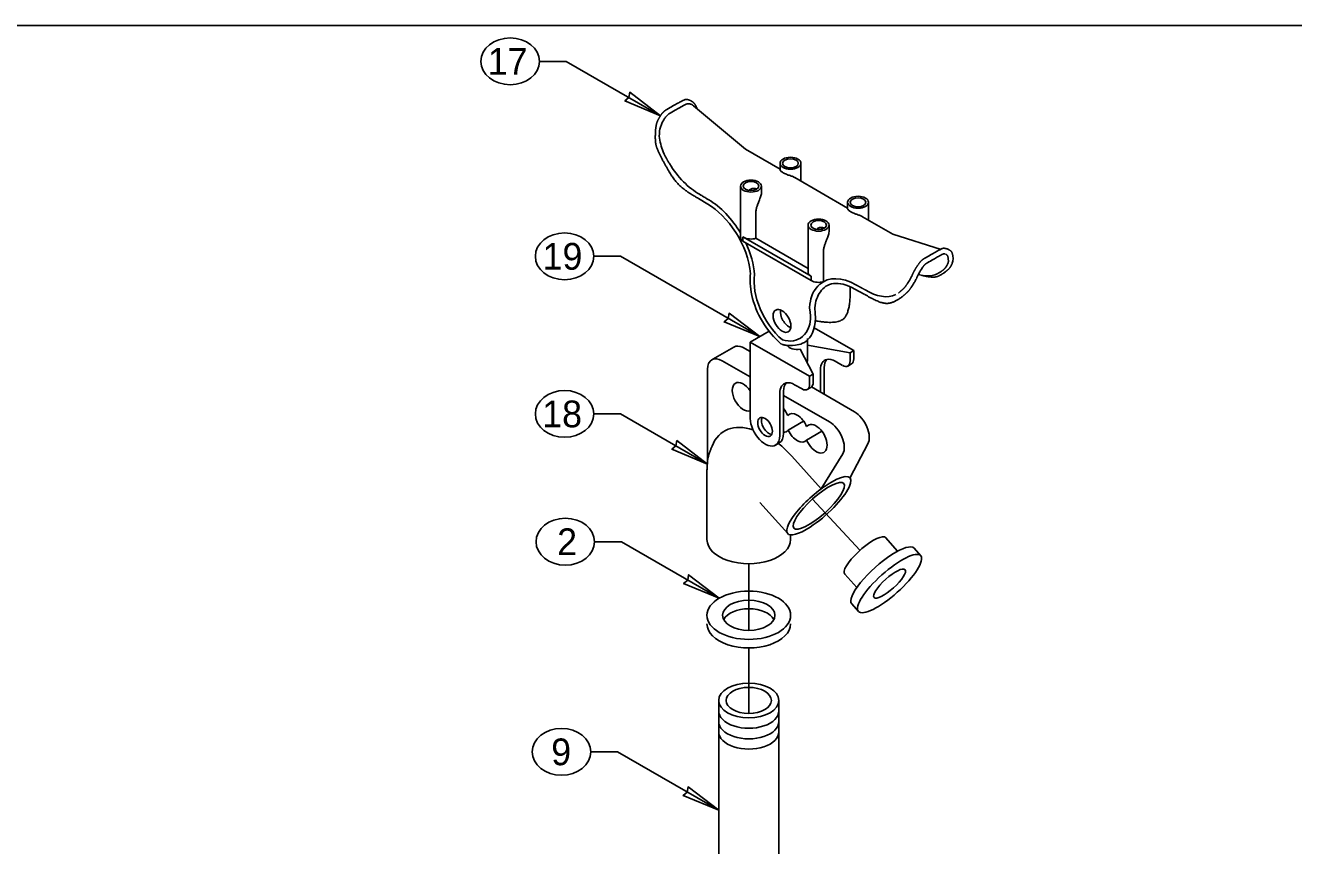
# Model space of a CAD drawing. Extents: x 99862 to 104211, y 98939 to 105076.
# Drawn here: x 100620 to 101379, y 104585 to 105076 of the extents above; entities that cross this region are included whole.
import ezdxf

# ---------------------------------------------------------------- set-up
doc = ezdxf.new("R2010")
doc.units = 0
for name, color, linetype in [('Level 1', 7, 'Continuous'), ('Level 11', 7, 'Continuous'), ('Level 15', 7, 'Continuous'), ('Level 17', 7, 'Continuous'), ('Level 18', 7, 'Continuous'), ('Level 19', 7, 'Continuous'), ('Level 2', 7, 'Continuous'), ('Level 20', 7, 'Continuous'), ('Level 4', 7, 'Continuous'), ('Level 5', 7, 'Continuous'), ('Level 6', 7, 'Continuous'), ('Level 9', 7, 'Continuous')]:
    doc.layers.add(name, color=color, linetype=linetype)

msp = doc.modelspace()

# ---------------------------------------------------------------- linework, layer by layer
at = {"layer": 'Level 1'}
msp.add_lwpolyline([(99862, 102999.5), (103151, 102999.5), (103151, 105075.5), (99862, 105075.5)], close=True, dxfattribs=at)
at = {"layer": 'Level 11'}
msp.add_ellipse((101053.04, 104722.69), major_axis=(15.62, 0), ratio=0.57735, dxfattribs=at)
for major_axis, start_param, end_param in [((-15.62, 0), 3.428349, 5.996429), ((-25, 0), 6.283185, 9.424778)]:
    msp.add_ellipse((101053.04, 104717.59), major_axis=major_axis, ratio=0.57735, start_param=start_param, end_param=end_param, dxfattribs=at)
at = {"layer": 'Level 15'}
for p, q in [((100927.89, 105053.96), (100943.89, 105053.96)), ((101000.18, 105021.46), (100943.89, 105053.96)), ((100960.4, 104937.38), (100976.4, 104937.38)), ((101059.56, 104889.37), (100976.4, 104937.38)), ((100960.4, 104843.13), (100976.4, 104843.13)), ((101028.35, 104813.14), (100976.4, 104843.13)), ((101119.52, 104761.57), (101091.2, 104792.24)), ((100960.83, 104766.69), (100976.83, 104766.69)), ((101035.37, 104732.9), (100976.83, 104766.69)), ((101053.04, 104713.67), (101053.04, 104753.52)), ((101053.04, 104664), (101053.04, 104703.15)), ((100958.51, 104641.04), (100974.51, 104641.04)), ((101035.04, 104606.09), (100974.51, 104641.04))]:
    msp.add_line(p, q, dxfattribs=at)
for points in [[(101000.18, 105021.46), (100978.92, 105030.29), (100981.33, 105032.35), (100981.9, 105035.46)], [(101059.56, 104889.37), (101038.29, 104898.2), (101040.7, 104900.26), (101041.28, 104903.37)], [(101028.35, 104813.14), (101007.08, 104821.97), (101009.49, 104824.03), (101010.07, 104827.14)], [(101035.37, 104732.9), (101014.1, 104741.72), (101016.51, 104743.78), (101017.09, 104746.9)], [(101035.04, 104606.09), (101013.78, 104614.92), (101016.19, 104616.97), (101016.77, 104620.09)]]:
    msp.add_lwpolyline(points, close=True, dxfattribs=at)
at = {"layer": 'Level 17'}
for p, q in [((101051.02, 105001.52), (101020.01, 105027.39)), ((101071.72, 104989.57), (101051.02, 105001.52)), ((101071.72, 104993.02), (101071.72, 104989.16)), ((101084.22, 104982.36), (101084.22, 104993.02)), ((101112.14, 104966.23), (101080.65, 104984.42)), ((101048.1, 104979.39), (101048.1, 104948.77)), ((101060.6, 104975.53), (101060.6, 104979.39)), ((101022.99, 104972.01), (101028.49, 104968.61)), ((101112.14, 104969.69), (101112.14, 104965.83)), ((101124.64, 104959.02), (101124.64, 104969.69)), ((101057.3, 104962.72), (101057.3, 104948.14)), ((101139.16, 104950.64), (101121.07, 104961.08)), ((101088.52, 104956.05), (101088.52, 104927.98)), ((101101.02, 104952.19), (101101.02, 104956.05)), ((101049.55, 104948.99), (101049.57, 104949)), ((101049.55, 104948.99), (101049.55, 104946.44)), ((101049.93, 104948.77), (101049.55, 104948.99)), ((101090.35, 104922.88), (101049.55, 104946.44)), ((101049.57, 104949), (101049.57, 104946.44)), ((101090.35, 104925.43), (101049.93, 104948.77)), ((101057.3, 104948.14), (101088.52, 104930.11)), ((101168.03, 104941.38), (101139.16, 104950.64)), ((101097.72, 104939.39), (101097.72, 104922.25)), ((101090.35, 104925.43), (101090.35, 104922.88)), ((101116.55, 104917.76), (101122.06, 104914.81))]:
    msp.add_line(p, q, dxfattribs=at)
for centre, major_axis, ratio, start_param, end_param in [((101022.89, 105004.42), (-17.72, 31.29), 0.57735, 1.6138, 2.395219), ((101029.05, 104939.26), (-19.52, 33.81), 0.57735, 4.736377, 5.49473), ((101054.35, 104948.77), (-6.25, 0), 0.57735, 6.283185, 6.98269), ((101054.35, 104951.32), (-6.25, 0), 0.57735, 0.699505, 0.785398), ((101054.35, 104951.32), (-6.25, 0), 0.57735, 0.785398, 2.061945), ((101029.05, 104939.26), (-19.52, 33.81), 0.57735, 4.022982, 4.565814), ((101078.65, 104909.31), (-15.86, 27.48), 0.57735, 0.616549, 2.107388), ((101094.77, 104927.98), (-6.25, 0), 0.57735, 6.283185, 7.068583), ((101094.77, 104925.43), (6.25, 0), 0.57735, 3.926991, 5.203538), ((101117.2, 104888.37), (-19.52, 33.81), 0.57735, 5.500844, 6.398051), ((101147.91, 104959.93), (-18.75, 32.48), 0.577329, 2.604955, 3.160056), ((101123.69, 104946.07), (-17.98, 31.14), 0.57735, 2.31717, 3.098589), ((101077.22, 104901.24), (3.75, -6.5), 0.57735, 3.754385, 5.670393), ((101067.6, 104915.69), (15.86, -27.48), 0.57735, 5.746594, 6.3945), ((101067.6, 104915.69), (15.86, -27.48), 0.57735, 0.13318472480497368, 0.13318473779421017)]:
    msp.add_ellipse(centre, major_axis=major_axis, ratio=ratio, start_param=start_param, end_param=end_param, dxfattribs=at)
for centre, major_axis in [((101077.97, 104993.02), (-6.25, 0)), ((101077.97, 104993.02), (-4.69, 0)), ((101054.35, 104979.39), (-6.25, 0)), ((101054.35, 104979.39), (4.69, 0)), ((101118.39, 104969.69), (6.25, 0)), ((101118.39, 104969.69), (4.69, 0)), ((101094.77, 104956.05), (6.25, 0)), ((101094.77, 104956.05), (-4.69, 0)), ((101072.91, 104898.75), (3.75, -6.5))]:
    msp.add_ellipse(centre, major_axis=major_axis, ratio=0.57735, dxfattribs=at)
for points, degree in [([(101017.26, 105030.92), (101015.78, 105031.33), (101014.12, 105030.99), (101004.13, 105025.26)], 2), ([(101017.78, 105028.53), (101017.28, 105028.63), (101016.75, 105028.63), (101015.62, 105028.42), (101015.02, 105028.2), (101005.99, 105023.01)], 3), ([(101022.01, 105026.11), (101020.95, 105028.32), (101019.39, 105030), (101017.26, 105030.92)], 2), ([(101020.01, 105027.38), (101019.34, 105027.95), (101018.61, 105028.35), (101017.78, 105028.53)], 2), ([(101000.08, 105021.29), (100998.54, 105018.73), (100997.57, 105015.8), (100997.31, 105012.91)], 2), ([(101004.13, 105025.26), (101002.69, 105024.39), (101001.31, 105023.06), (101000.08, 105021.29)], 2), ([(101005.99, 105023.01), (101005.41, 105022.65), (101004.81, 105022.18), (101003.69, 105021.1), (101003.16, 105020.48), (101002.66, 105019.81)], 3), ([(100997.32, 105012.91), (100996.88, 105007.06), (100998.19, 105001.07), (101001.03, 104995.89)], 2), ([(101002.66, 105019.81), (101001.93, 105018.73), (101001.32, 105017.53), (101000.35, 105015.05), (101000, 105013.77), (100999.73, 105012.49)], 3), ([(100999.73, 105012.49), (100999.4, 105009.8), (100999.68, 105007.09), (101000.99, 105001.85), (101002.01, 104999.32), (101003.28, 104996.91)], 3), ([(101001.05, 104995.86), (101006.35, 104985.51), (101014.62, 104976.49), (101022.99, 104972.01)], 2), ([(101003.28, 104996.91), (101003.55, 104996.4), (101003.83, 104995.9), (101004.12, 104995.4)], 2), ([(101004.12, 104995.4), (101004.55, 104994.51), (101005.05, 104993.67), (101005.6, 104992.86)], 2), ([(101080.66, 104984.41), (101080.42, 104984.55), (101080.16, 104984.68), (101079.27, 104985.09), (101078.56, 104985.36), (101077.08, 104985.87), (101076.29, 104986.14), (101074.83, 104986.72), (101074.14, 104987.03), (101072.99, 104987.69), (101072.53, 104988.04), (101071.91, 104988.67), (101071.75, 104988.95), (101071.72, 104989.14), (101071.72, 104989.15), (101071.72, 104989.16)], 3), ([(101057.75, 104977.52), (101057.72, 104977.54), (101057.7, 104977.55), (101057.18, 104977.86), (101056.57, 104978), (101055.3, 104977.97), (101054.65, 104977.79), (101053.7, 104977.28), (101053.37, 104977.05), (101053.06, 104976.78)], 3), ([(101057.3, 104962.72), (101057.23, 104964.14), (101057.42, 104965.5), (101058.03, 104967.61), (101058.29, 104968.32), (101058.85, 104969.76), (101059.17, 104970.51), (101059.76, 104972), (101060.05, 104972.77), (101060.46, 104974.21), (101060.59, 104974.9), (101060.6, 104975.54)], 3), ([(101023.63, 104974.5), (101024.75, 104973.81), (101025.87, 104973.12), (101026.98, 104972.43), (101027.7, 104971.98), (101028.42, 104971.54), (101029.14, 104971.09)], 3), ([(101028.53, 104968.58), (101034.15, 104965.32), (101046.76, 104952.94), (101053.4, 104935.26), (101054.06, 104926.95)], 3), ([(101112.14, 104965.83), (101112.14, 104965.82), (101112.14, 104965.81), (101112.16, 104965.62), (101112.32, 104965.34), (101112.94, 104964.71), (101113.39, 104964.37), (101114.54, 104963.71), (101115.22, 104963.39), (101116.69, 104962.81), (101117.47, 104962.55), (101118.96, 104962.03), (101119.67, 104961.76), (101120.58, 104961.35), (101120.84, 104961.21), (101121.09, 104961.07)], 3), ([(101098.17, 104954.19), (101098.14, 104954.2), (101098.12, 104954.22), (101097.6, 104954.52), (101096.99, 104954.67), (101095.72, 104954.63), (101095.06, 104954.45), (101094.11, 104953.94), (101093.79, 104953.71), (101093.48, 104953.45)], 3), ([(101101.02, 104952.16), (101101, 104951.54), (101100.88, 104950.87), (101100.48, 104949.44), (101100.2, 104948.69), (101099.3, 104946.44), (101098.67, 104944.99), (101098.05, 104942.87), (101097.89, 104942.19), (101097.72, 104940.84), (101097.7, 104940.17), (101097.72, 104939.39)], 3), ([(101158.25, 104936.22), (101168.3, 104941.99), (101169.94, 104942.32), (101171.63, 104941.83)], 2), ([(101159.84, 104933.53), (101168.81, 104938.69), (101169.99, 104939.02), (101170.49, 104938.92)], 2), ([(101171.04, 104938.6), (101171.71, 104938.07), (101172.12, 104937.3), (101172.23, 104936.32)], 2), ([(101171.63, 104941.83), (101173.52, 104941.06), (101174.83, 104939.34), (101175.11, 104937.29)], 2), ([(101175.1, 104937.29), (101175.31, 104935.97), (101175.14, 104934.32), (101174.58, 104932.95), (101174.46, 104932.67)], 3), ([(101150.39, 104925.2), (101151.37, 104927.52), (101152.74, 104930.03), (101154.3, 104932.38)], 2), ([(101153.25, 104923.95), (101153.68, 104924.96), (101154.72, 104927.16), (101156.12, 104929.48), (101156.9, 104930.66)], 3), ([(101154.35, 104932.45), (101155.46, 104934.04), (101156.85, 104935.38), (101158.29, 104936.25)], 2), ([(101156.9, 104930.66), (101157.78, 104931.9), (101158.84, 104932.93), (101159.87, 104933.55)], 2), ([(101171.27, 104931.52), (101170.72, 104930.6), (101169.94, 104929.73), (101168.95, 104928.95)], 2), ([(101174.46, 104932.67), (101173.74, 104931.07), (101172.56, 104929.68), (101170.98, 104928.45)], 2), ([(101172.23, 104936.32), (101172.49, 104934.67), (101172.18, 104933.02), (101171.27, 104931.52)], 2), ([(101054.06, 104927.02), (101053.61, 104923.77), (101053.92, 104914.3), (101060.2, 104898.14), (101068.38, 104888.37), (101072.44, 104884.93)], 3), ([(101142.54, 104915.48), (101145.42, 104917.71), (101148.01, 104921), (101150.41, 104925.24)], 2), ([(101145.15, 104913.54), (101147.85, 104915.68), (101150.62, 104919.26), (101153.25, 104923.95)], 2), ([(101170.97, 104928.44), (101167.18, 104925.41), (101162.06, 104924.66), (101156.59, 104925.98)], 2), ([(101168.95, 104928.95), (101168.34, 104928.45), (101167.69, 104928.02), (101167, 104927.66)], 2), ([(101089.42, 104906.78), (101089.89, 104912.44), (101092.01, 104917.46), (101095.41, 104920.52), (101095.57, 104920.67)], 3), ([(101092.54, 104906.59), (101092.86, 104910.29), (101095.1, 104917.02), (101102.85, 104922.41), (101111.52, 104920.64), (101116.51, 104917.79)], 3), ([(101092.59, 104898.91), (101107.43, 104896.05), (101114.14, 104906.37), (101113.56, 104919.27)], 2), ([(101117.11, 104920.3), (101118.95, 104919.32), (101120.78, 104918.33), (101122.62, 104917.35)], 2), ([(101122.01, 104914.85), (101130.46, 104909.59), (101139.36, 104908.91), (101145.14, 104913.53)], 2), ([(101076.2, 104884.06), (101076.68, 104884.01), (101080.19, 104883.68), (101090.16, 104886.31), (101093.62, 104897.63), (101092.54, 104906.59)], 3), ([(101085.13, 104889.4), (101085.24, 104889.49), (101088.83, 104892.79), (101090.43, 104899.24), (101089.42, 104906.63)], 3), ([(101072.63, 104884.83), (101073.82, 104884.47), (101074.97, 104884.21), (101076.18, 104884.06)], 2)]:
    msp.add_open_spline(points, degree=degree, dxfattribs=at)
at = {"layer": 'Level 18'}
for p, q in [((101044.14, 104883.11), (101031.47, 104875.79)), ((101049.36, 104883.01), (101053.94, 104880.37)), ((101028.35, 104813.14), (101028.35, 104869.81)), ((101037.18, 104874.91), (101053.94, 104865.24)), ((101073.83, 104854.23), (101101.3, 104838.37)), ((101090.53, 104859.25), (101116.26, 104844.39)), ((101124.27, 104825.23), (101113.57, 104805.04)), ((101096.26, 104798.26), (101078.78, 104817.81)), ((101109.31, 104819.21), (101096.26, 104798.26)), ((101028.04, 104807.82), (101028.04, 104767.96)), ((101059.58, 104790.22), (101076.3, 104771.53)), ((101078.04, 104767.96), (101078.04, 104770.77)), ((101134.84, 104769.15), (101142.07, 104761.06)), ((101155.85, 104758.34), (101151.85, 104762.81)), ((101110.45, 104747.2), (101117.57, 104739.24)), ((101114.58, 104729.48), (101118.58, 104725))]:
    msp.add_line(p, q, dxfattribs=at)
for centre, major_axis, ratio, start_param, end_param in [((101050.39, 104872.28), (-6.25, 10.83), 0.57735, 5.614919, 6.283185), ((101037.18, 104864.7), (-6.25, 10.83), 0.57735, 5.497787, 7.068583), ((101049.8, 104853.4), (-4.69, 8.12), 0.57735, 4.823124, 9.314051), ((101070.74, 104841.3), (-4.69, 8.12), 0.57735, 4.483455, 5.013808), ((101082, 104834.8), (-4.69, 8.12), 0.57735, 4.483455, 6.512119), ((101101.3, 104828.16), (6.25, -10.83), 0.57735, 0.347397, 2.356194), ((101116.26, 104834.18), (6.25, -10.83), 0.57735, 0.347397, 2.356194), ((101061.88, 104792.51), (-23.33, 40.4), 0.57735, 5.689816, 6.702979), ((101070.97, 104840.77), (-4.69, 8.12), 0.57735, 2.801217, 3.370527), ((101082, 104834.8), (-4.69, 8.12), 0.57735, 1.404224, 3.370527), ((101093.26, 104828.3), (-4.69, 8.12), 0.57735, 1.341862, 6.512119), ((101064.79, 104791.4), (-23.33, 40.4), 0.57735, 5.059786, 5.31784), ((101094.93, 104788.2), (-18.63, -16.67), 0.277977, 4.067589, 7.338126), ((101094.93, 104788.2), (-18.63, -16.67), 0.277977, 1.054941, 4.067589), ((101122.61, 104758.21), (12.23, 10.94), 0.277977, 0.174514, 3.16344), ((101053.04, 104767.96), (-25, 0), 0.57735, 6.283185, 9.424778), ((101133.22, 104746.15), (18.63, 16.67), 0.277977, 6.283185, 9.424778), ((101122.61, 104758.21), (12.23, 10.94), 0.277977, 6.283183, 6.457699)]:
    msp.add_ellipse(centre, major_axis=major_axis, ratio=ratio, start_param=start_param, end_param=end_param, dxfattribs=at)
for major_axis in [(18.63, 16.67), (9.28, 8.3)]:
    msp.add_ellipse((101137.22, 104741.67), major_axis=major_axis, ratio=0.277977, dxfattribs=at)
msp.add_open_spline([(101031.06, 104823.89), (101028.99, 104818.82), (101028.04, 104813.35), (101028.04, 104807.82)], degree=2, dxfattribs=at)
at = {"layer": 'Level 19'}
for p, q in [((101065.18, 104892.61), (101053.94, 104886.12)), ((101065.18, 104892.61), (101053.94, 104886.12)), ((101091.78, 104894.89), (101115.81, 104881.02)), ((101053.94, 104886.12), (101053.94, 104840.43)), ((101053.94, 104886.12), (101053.94, 104840.43)), ((101053.94, 104886.12), (101089.29, 104865.71)), ((101113.6, 104879.74), (101088.11, 104884.22)), ((101091.5, 104866.99), (101083.67, 104881.86)), ((101115.81, 104881.02), (101113.6, 104879.74)), ((101113.6, 104877.19), (101113.6, 104879.74)), ((101113.6, 104874.82), (101113.6, 104877.19)), ((101115.81, 104881.02), (101115.81, 104876.09)), ((101095.92, 104863.18), (101095.92, 104869.54)), ((101098.13, 104870.81), (101098.13, 104864.45)), ((101109.18, 104872.09), (101104.76, 104874.64)), ((101114.52, 104873.05), (101112.31, 104871.78)), ((101089.29, 104865.71), (101091.5, 104866.99)), ((101089.29, 104865.71), (101089.29, 104860.78)), ((101091.5, 104864.44), (101091.5, 104866.99)), ((101091.5, 104862.06), (101091.5, 104864.44)), ((101095.92, 104856.13), (101095.92, 104863.18)), ((101098.13, 104864.45), (101098.13, 104854.86)), ((101071.62, 104849.14), (101071.62, 104855.5)), ((101073.83, 104850.42), (101073.83, 104856.78)), ((101073.83, 104850.42), (101073.83, 104856.78)), ((101080.46, 104860.61), (101084.88, 104858.05)), ((101080.46, 104860.61), (101084.88, 104858.05)), ((101088, 104857.75), (101090.21, 104859.02)), ((101071.61, 104830.32), (101071.62, 104849.14)), ((101073.82, 104831.6), (101073.83, 104850.42)), ((101073.82, 104831.6), (101073.83, 104850.42)), ((101069.03, 104824.5), (101071.24, 104825.78)), ((101069.03, 104824.5), (101071.24, 104825.78))]:
    msp.add_line(p, q, dxfattribs=at)
for centre, major_axis, start_param, end_param in [((101081.86, 104885.31), (6.25, 0), 3.488598, 5.007384), ((101104.76, 104864.43), (6.25, -10.83), 2.356194, 2.965861), ((101111.39, 104878.47), (3.13, -5.41), 0, 0.820027), ((101104.76, 104864.43), (6.25, -10.83), 2.965861, 3.926991), ((101106.97, 104865.71), (6.25, -10.83), 3.319303, 3.926991), ((101109.18, 104877.19), (3.13, -5.41), 5.497787, 6.323034), ((101109.18, 104877.19), (3.13, -5.41), 0.039849, 0.820027), ((101080.46, 104850.4), (6.25, -10.83), 2.97025, 3.926991), ((101082.67, 104851.68), (6.25, -10.83), 3.319303, 3.926991), ((101082.67, 104851.68), (6.25, -10.83), 3.319303, 3.926991), ((101080.46, 104850.4), (6.25, -10.83), 2.356194, 2.97025), ((101080.46, 104850.4), (6.25, -10.83), 2.356194, 2.97025), ((101087.09, 104864.43), (3.13, -5.41), 0, 0.820027), ((101084.88, 104863.16), (3.13, -5.41), 5.497787, 6.369012), ((101084.88, 104863.16), (3.13, -5.41), 0.085827, 0.820027), ((101062.78, 104835.33), (6.25, -10.83), 3.927, 6.298242), ((101062.78, 104835.33), (6.25, -10.83), 3.927, 6.298242), ((101064.99, 104836.6), (3.13, -5.41), 3.50296, 5.921818), ((101064.99, 104836.6), (6.25, -10.83), 0, 0.795013), ((101064.99, 104836.6), (6.25, -10.83), 0, 0.795013), ((101062.78, 104835.33), (6.25, -10.83), 0.015056, 0.795013)]:
    msp.add_ellipse(centre, major_axis=major_axis, ratio=0.57735, start_param=start_param, end_param=end_param, dxfattribs=at)
msp.add_ellipse((101062.78, 104835.33), major_axis=(3.13, -5.41), ratio=0.57735, dxfattribs=at)
at = {"layer": 'Level 2'}
msp.add_ellipse((101053.04, 104722.69), major_axis=(25, 0), ratio=0.57735, dxfattribs=at)
at = {"layer": 'Level 20'}
for centre in [(100910.39, 105053.96), (100942.9, 104937.38), (100942.9, 104843.13), (100943.33, 104766.69), (100941.01, 104641.04)]:
    msp.add_ellipse(centre, major_axis=(-17.5, 0), ratio=0.8, dxfattribs=at)
at = {"layer": 'Level 4'}
msp.add_line((101088.11, 104875.11), (101088.11, 104888.17), dxfattribs=at)
msp.add_ellipse((101081.86, 104875.11), major_axis=(6.25, 0), ratio=0.57735, start_param=5.972868, end_param=6.283185, dxfattribs=at)
at = {"layer": 'Level 5'}
for p, q in [((101076.6, 104833.48), (101085.84, 104838.82)), ((101087.63, 104827.51), (101096.76, 104832.78))]:
    msp.add_line(p, q, dxfattribs=at)
msp.add_ellipse((101094.93, 104788.2), major_axis=(-14.91, -13.33), ratio=0.277977, dxfattribs=at)
at = {"layer": 'Level 6'}
msp.add_ellipse((101053.04, 104671.79), major_axis=(13.5, 0), ratio=0.57735, dxfattribs=at)
at = {"layer": 'Level 9'}
for p, q in [((101035.04, 104671.79), (101035.04, 104540.01)), ((101071.04, 104540.01), (101071.04, 104671.79))]:
    msp.add_line(p, q, dxfattribs=at)
msp.add_ellipse((101053.04, 104671.79), major_axis=(18, 0), ratio=0.57735, dxfattribs=at)
for centre, start_param in [((101053.04, 104665.51), 3.141588), ((101053.04, 104659.19), 3.141587), ((101053.04, 104653.06), 3.141585)]:
    msp.add_ellipse(centre, major_axis=(18, 0), ratio=0.57735, start_param=start_param, end_param=6.283185, dxfattribs=at)

# ---------------------------------------------------------------- texts
at = {"layer": 'Level 20'}
for s, p in [('17', (100896.94, 105045.96)), ('19', (100929.74, 104929.38)), ('18', (100929.52, 104835.13)), ('9', (100934.91, 104633.04))]:
    msp.add_text(s, height=16, dxfattribs=at).set_placement(p)
msp.add_text('2', height=16, rotation=360, dxfattribs=at).set_placement((100938.45, 104758.69))

doc.saveas('drawing.dxf')
